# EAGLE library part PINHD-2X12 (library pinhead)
PIN HEADER
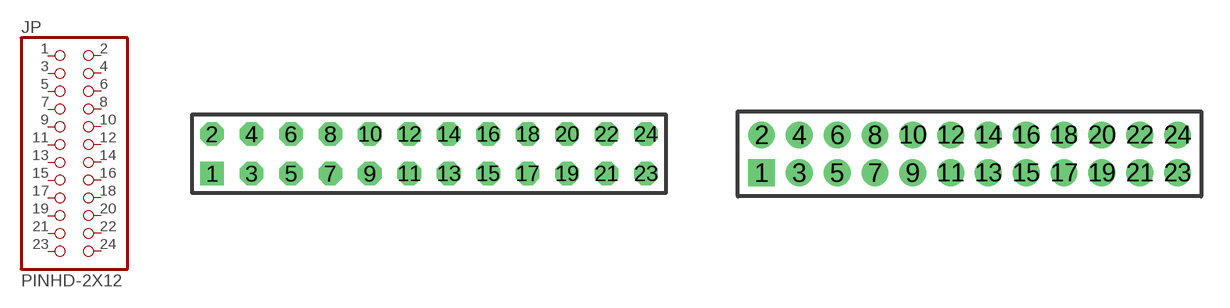
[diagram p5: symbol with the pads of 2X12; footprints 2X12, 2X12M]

Designator prefix JP

## PINHD-2X12  [2X12]
1  1  pas
2  2  pas
3  3  pas
4  4  pas
5  5  pas
6  6  pas
7  7  pas
8  8  pas
9  9  pas
10  10  pas
11  11  pas
12  12  pas
13  13  pas
14  14  pas
15  15  pas
16  16  pas
17  17  pas
18  18  pas
19  19  pas
20  20  pas
21  21  pas
22  22  pas
23  23  pas
24  24  pas

## PINHD-2X12M  [2X12M]
Pads as for 2X12

## Footprint 2X12 (pad centres in mm)
PIN HEADER - 0.1"
drill 1.016 square: 1 -13.97,-1.27
drill 1.016 octagon: 2 -13.97,1.27; 3 -11.43,-1.27; 4 -11.43,1.27; 5 -8.89,-1.27; 6 -8.89,1.27; 7 -6.35,-1.27; 8 -6.35,1.27; 9 -3.81,-1.27; 10 -3.81,1.27; 11 -1.27,-1.27; 12 -1.27,1.27; 13 1.27,-1.27; 14 1.27,1.27; 15 3.81,-1.27; 16 3.81,1.27; 17 6.35,-1.27; 18 6.35,1.27; 19 8.89,-1.27; 20 8.89,1.27; 21 11.43,-1.27; 22 11.43,1.27; 23 13.97,-1.27; 24 13.97,1.27

## Footprint 2X12M (pad centres in mm)
PIN HEADER - 2MM"
drill 0.914 square: 1 -11,-1
drill 0.914 round: 2 -11,1; 3 -9,-1; 4 -9,1; 5 -7,-1; 6 -7,1; 7 -5,-1; 8 -5,1; 9 -3,-1; 10 -3,1; 11 -1,-1; 12 -1,1; 13 1,-1; 14 1,1; 15 3,-1; 16 3,1; 17 5,-1; 18 5,1; 19 7,-1; 20 7,1; 21 9,-1; 22 9,1; 23 11,-1; 24 11,1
